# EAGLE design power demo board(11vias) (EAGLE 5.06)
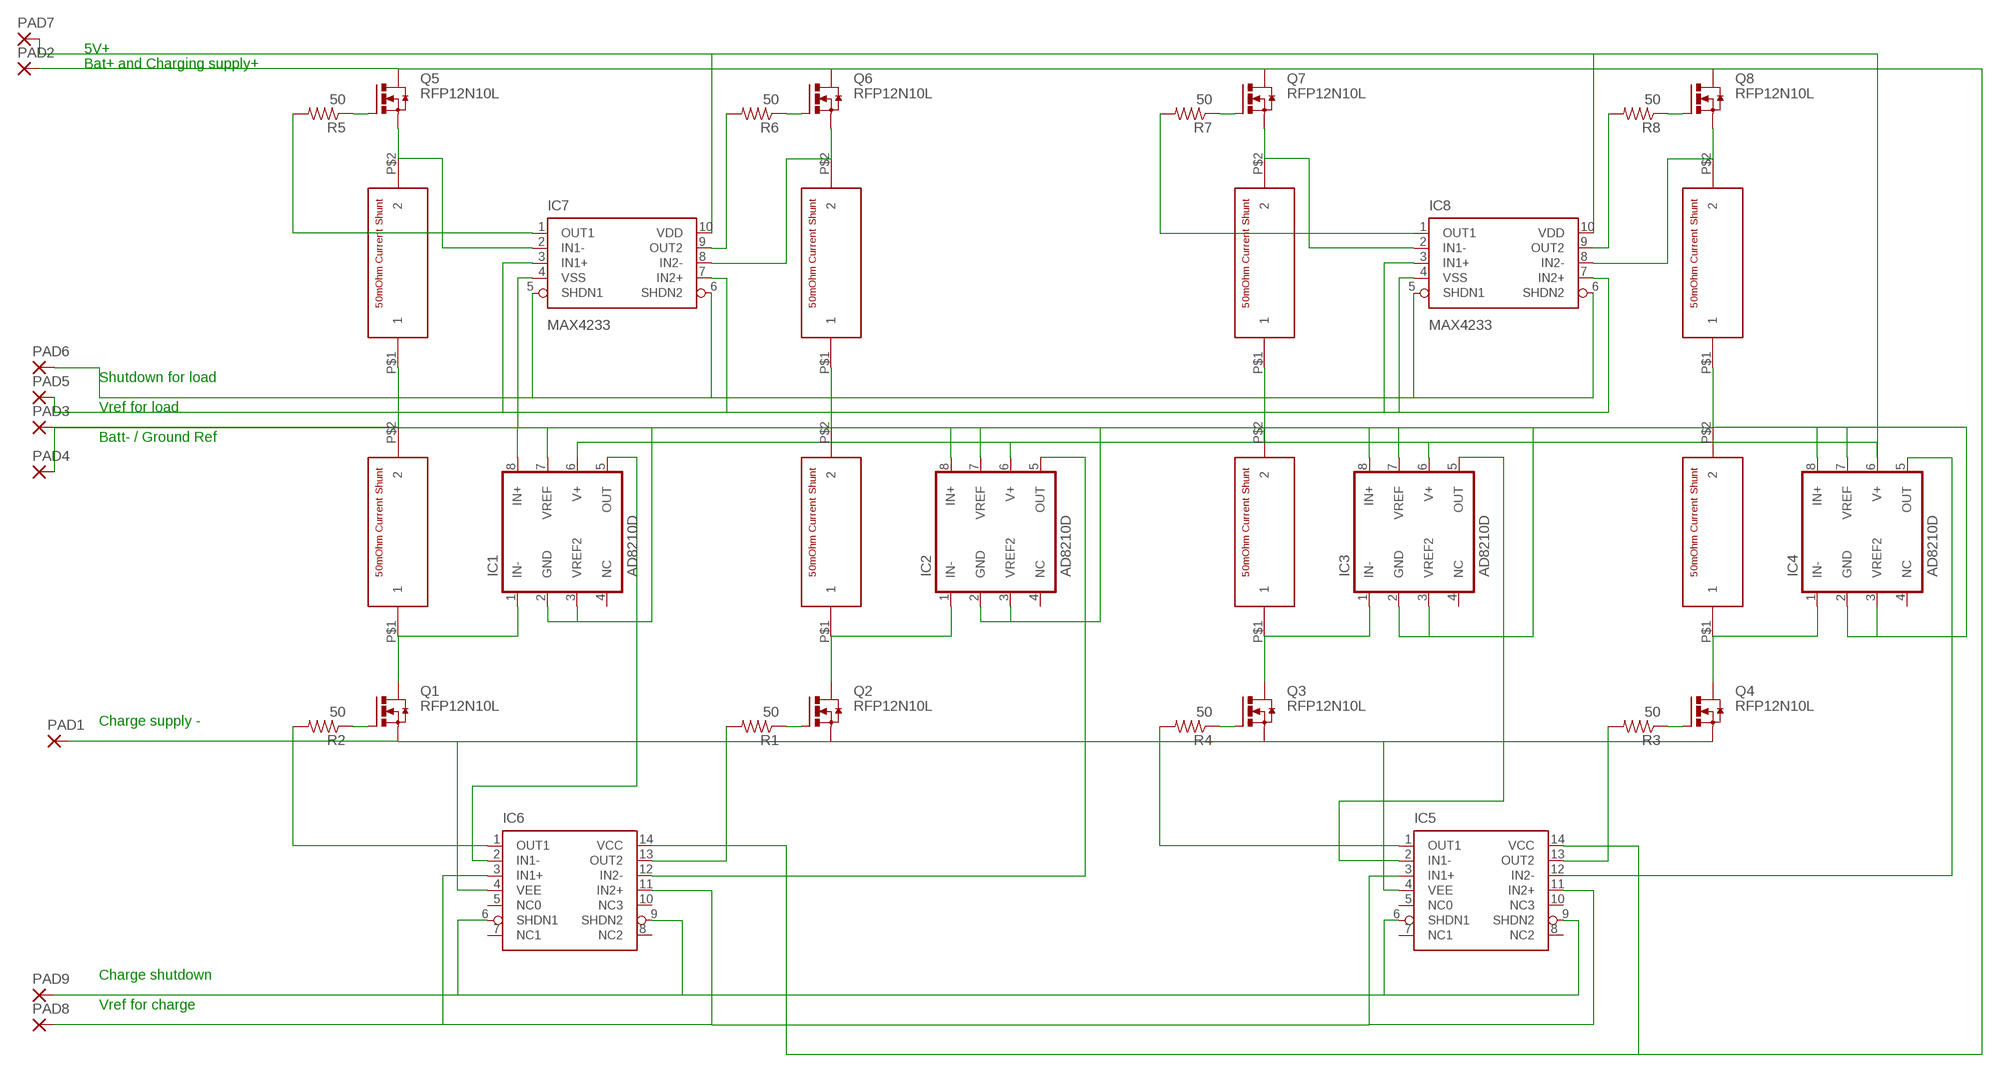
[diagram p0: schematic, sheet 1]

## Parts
IC1  AD8210D  [SO08]
IC2  AD8210D  [SO08]
IC3  AD8210D  [SO08]
IC4  AD8210D  [SO08]
IC5  MAX4168D  [SO14]
IC6  MAX4168D  [SO14]
IC7  MAX4233  [UMAX10]
IC8  MAX4233  [UMAX10]
PAD1  3,81/1,4  [3,81/1,4]
PAD2  3,81/1,4  [3,81/1,4]
PAD3  3,81/1,4  [3,81/1,4]
PAD4  3,81/1,4  [3,81/1,4]
PAD5  3,17/1,1  [3,17/1,1]
PAD6  3,17/1,1  [3,17/1,1]
PAD7  3,17/1,1  [3,17/1,1]
PAD8  3,17/1,1  [3,17/1,1]
PAD9  3,17/1,1  [3,17/1,1]
Q1  RFP12N10L  [TO220-W/657-20ABP]
Q2  RFP12N10L  [TO220-W/657-20ABP]
Q3  RFP12N10L  [TO220-W/657-20ABP]
Q4  RFP12N10L  [TO220-W/657-20ABP]
Q5  RFP12N10L  [TO220-W/657-20ABP]
Q6  RFP12N10L  [TO220-W/657-20ABP]
Q7  RFP12N10L  [TO220-W/657-20ABP]
Q8  RFP12N10L  [TO220-W/657-20ABP]
R1  50  R-US_0207/10  [0207/10]
R2  50  R-US_0207/10  [0207/10]
R3  50  R-US_0207/10  [0207/10]
R4  50  R-US_0207/10  [0207/10]
R5  50  R-US_0207/10  [0207/10]
R6  50  R-US_0207/10  [0207/10]
R7  50  R-US_0207/10  [0207/10]
R8  50  R-US_0207/10  [0207/10]
U$1  630HR050E  [630HR050E]
U$2  630HR050E  [630HR050E]
U$3  630HR050E  [630HR050E]
U$4  630HR050E  [630HR050E]
U$5  630HR050E  [630HR050E]
U$6  630HR050E  [630HR050E]
U$7  630HR050E  [630HR050E]
U$8  630HR050E  [630HR050E]

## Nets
N$1: IC5.13(OUT2) R3.2
N$2: IC1.1(IN-) Q1.2(D) U$5.P$1
N$3: IC2.1(IN-) Q2.2(D) U$6.P$1
N$4: IC3.1(IN-) Q3.2(D) U$7.P$1
N$5: IC7.3(IN1+) IC7.7(IN2+) IC8.3(IN1+) IC8.4(VSS) IC8.7(IN2+) PAD5.1(P)
N$6: IC5.4(VEE) IC6.4(VEE) PAD1.1(P) Q1.3(S) Q2.3(S) Q3.3(S) Q4.3(S)
N$7: IC7.2(IN1-) Q5.3(S) U$1.P$2
N$8: IC7.8(IN2-) Q6.3(S) U$2.P$2
N$9: IC8.2(IN1-) Q7.3(S) U$3.P$2
N$10: IC8.8(IN2-) Q8.3(S) U$4.P$2
N$11: IC5.14(VCC) IC6.14(VCC) PAD2.1(P) Q5.2(D) Q6.2(D) Q7.2(D) Q8.2(D)
N$12: IC7.1(OUT1) R5.2
N$13: Q5.1(G) R5.1
N$14: IC7.9(OUT2) R6.2
N$15: Q6.1(G) R6.1
N$16: Q7.1(G) R7.1
N$17: IC8.1(OUT1) R7.2
N$18: Q8.1(G) R8.1
N$19: IC8.9(OUT2) R8.2
N$20: IC7.5(SHDN1) IC7.6(SHDN2) IC8.5(SHDN1) IC8.6(SHDN2) PAD6.1(P)
N$21: IC4.1(IN-) Q4.2(D) U$8.P$1
N$22: IC5.6(SHDN1) IC5.9(SHDN2) IC6.6(SHDN1) IC6.9(SHDN2) PAD9.1(P)
N$23: IC6.13(OUT2) R1.2
N$24: Q1.1(G) R2.1
N$25: Q2.1(G) R1.1
N$26: Q3.1(G) R4.1
N$27: Q4.1(G) R3.1
N$28: IC5.1(OUT1) R4.2
N$29: IC2.5(OUT) IC6.12(IN2-)
N$31: IC5.3(IN1+) IC5.11(IN2+) IC6.3(IN1+) IC6.11(IN2+) PAD8.1(P)
N$32: IC1.5(OUT) IC6.2(IN1-)
N$33: IC6.1(OUT1) R2.2
N$34: IC4.5(OUT) IC5.12(IN2-)
N$35: IC3.5(OUT) IC5.2(IN1-)
N$36: IC1.2(GND) IC1.3(VREF2) IC1.7(VREF) IC1.8(IN+) IC2.2(GND) IC2.3(VREF2) IC2.7(VREF) IC2.8(IN+) IC3.2(GND) IC3.3(VREF2) IC3.7(VREF) IC3.8(IN+) IC4.2(GND) IC4.3(VREF2) IC4.7(VREF) IC4.8(IN+) IC7.4(VSS) PAD3.1(P) PAD4.1(P) U$1.P$1 U$2.P$1 U$3.P$1 U$4.P$1 U$5.P$2 U$6.P$2 U$7.P$2 U$8.P$2
N$40: IC1.6(V+) IC2.6(V+) IC3.6(V+) IC4.6(V+) IC7.10(VDD) IC8.10(VDD) PAD7.1(P)
Unconnected: IC5.5(NC0) IC5.7(NC1) IC5.10(NC3) IC6.5(NC0) IC6.7(NC1) IC6.10(NC3)

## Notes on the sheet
- 5V+
- Bat+ and Charging supply+
- Shutdown for load
- Vref for load
- Batt- / Ground Ref
- Charge supply -
- Charge shutdown
- Vref for charge

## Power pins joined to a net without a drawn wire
NC: IC1.4(NC) IC2.4(NC) IC3.4(NC) IC4.4(NC)
NC2: IC5.8(NC2) IC6.8(NC2)

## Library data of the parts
IC1-IC4 = NEWPARTS:AD8210: High Voltage, Bidirectional Current Shunt Monitor
IC5 IC6 = NEWPARTS:MAX4168: High-Output-Drive, Precision, Low-power, Single-Supply, Rail-to-Rail I/O Op Amps with Shutdown
IC7 IC8 = NEWPARTS:MAX4233: High-Output-Drive, 10MHz, 10V/us, Rail-to_rail I/O Op Amps with Shutdown in SC70
PAD1-PAD4 = wirepad:3,81/1,4: THROUGH-HOLE PAD
PAD5-PAD9 = wirepad:3,17/1,1: THROUGH-HOLE PAD
Q1-Q8 = NEWPARTS:RFP12N10L: N-Channel Power MOSFET 100V; 12A; 0,2Ohm< Logic Level
R1-R8 = rcl:R-US_: RESISTOR, American symbol
U$1-U$8 = NEWPARTS:630HR050E

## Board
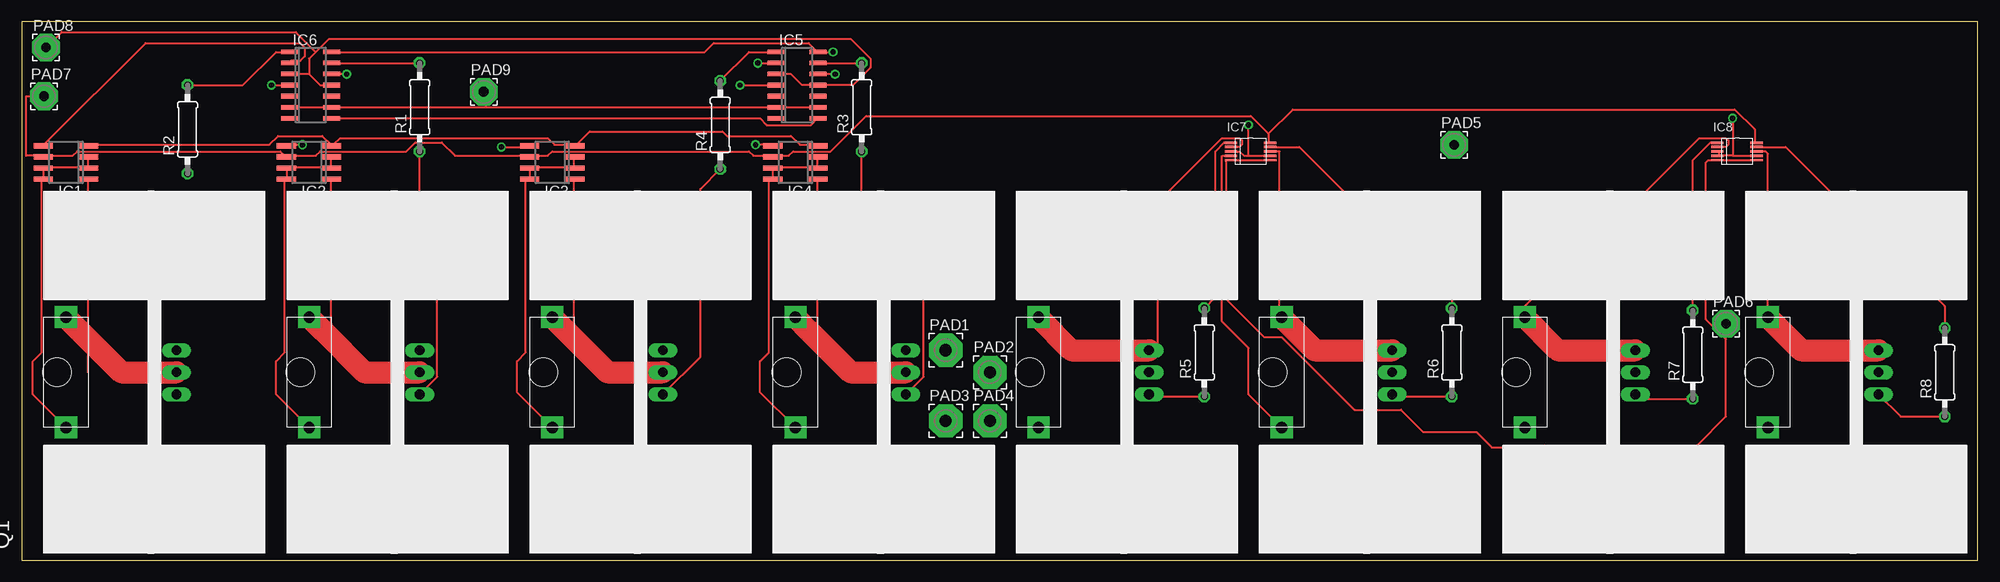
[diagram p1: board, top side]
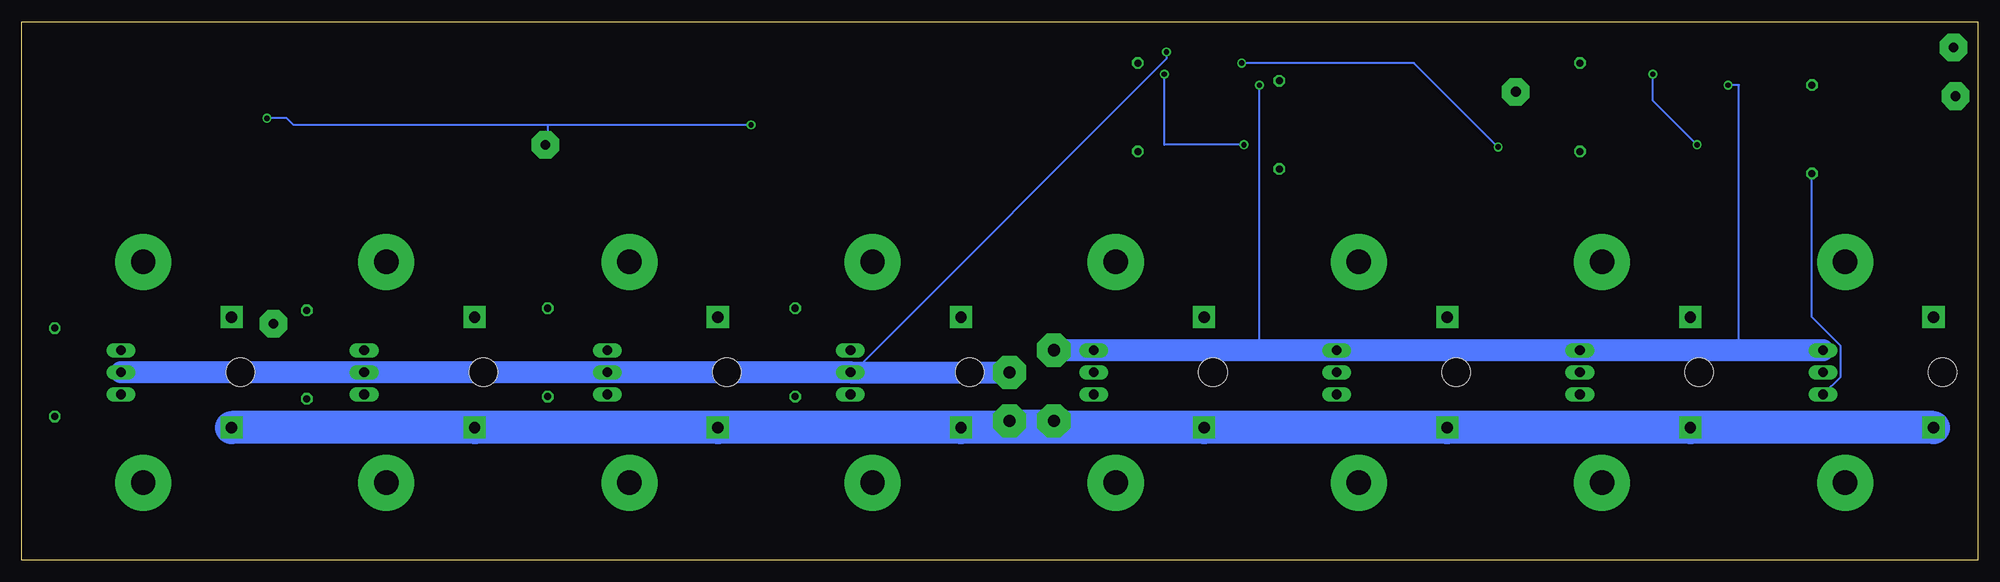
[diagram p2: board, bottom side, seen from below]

Size 224.77 x 61.9 mm. Coordinates in mm from the lower left corner, seen from the top.
Outline: 0,0 224.77,0 224.77,61.9 0,61.9 0,0
Copper layers (1*16): Top 0.035mm / dielectric 1.5mm / Bottom 0.035mm
Design rules "default *": minimum track width 10mil, minimum drill 24mil, track to track 10mil, track to pad 10mil, pad to pad 10mil, via to via 10mil, smd to smd 10mil, copper to edge 40mil, drill to drill 10mil, minimum pad ring 10mil, minimum via ring 8mil, stop-mask expansion 4mil, vias tented up to drill 0mil, thermal gap 10mil

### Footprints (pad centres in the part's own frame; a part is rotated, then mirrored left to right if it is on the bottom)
SO08 = smd 0.6 x 2.2: 1 -1.905,-2.6; 2 -0.635,-2.6; 3 0.635,-2.6; 4 1.905,-2.6; 5 1.905,2.6; 6 0.635,2.6; 7 -0.635,2.6; 8 -1.905,2.6
SO14 = smd 0.533 x 1.981: 1 -3.81,-2.219; 2 -2.54,-2.219; 3 -1.27,-2.219; 4 0,-2.219; 5 1.27,-2.219; 6 2.54,-2.219; 7 3.81,-2.219; 8 3.81,2.6; 9 2.54,2.6; 10 1.27,2.6; 11 0,2.6; 12 -1.27,2.6; 13 -2.54,2.6; 14 -3.81,2.6
UMAX10 = smd 0.28 x 1.4: 1 -1,-2; 2 -0.5,-2; 3 0,-2; 4 0.5,-2; 5 1,-2; 6 1,2.5; 7 0.5,2.5; 8 0,2.5; 9 -0.5,2.5; 10 -1,2.5
3,81/1,4 = drill 1.397 pad 3.81 octagon: 1 0,0
3,17/1,1 = drill 1.118 pad 3.175 octagon: 1 0,0
TO220-W/657-20ABP = drill 1.118 long: 1 -2.54,-2.54; 2 0,-2.54; 3 2.54,-2.54 | drill 2.8 pad 6.452 round: P$1 -12.7,0; P$2 12.7,0 | hole 3.302: 0,11.176
0207/10 = drill 0.813 octagon: 1 -5.08,0; 2 5.08,0
630HR050E = drill 1.3 pad 2.54 square: P$1 -6.35,0; P$2 6.35,0

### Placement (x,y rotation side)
IC1  5.08,45.72 90 top
IC2  33.02,45.72 90 top
IC3  60.96,45.72 90 top
IC4  88.9,45.72 90 top
IC5  88.9,54.61 270 top
IC6  33.02,54.61 270 top
IC7  140.97,46.99 270 top
IC8  196.85,46.99 270 top
PAD1  106.17,24.13 0 top
PAD2  111.25,21.59 0 top
PAD3  106.17,16 0 top
PAD4  111.25,16 0 top
PAD5  164.59,47.75 0 top
PAD6  195.83,27.18 0 top
PAD7  2.54,53.34 0 top
PAD8  2.79,58.93 0 top
PAD9  53.09,53.85 0 top
Q1  15.24,21.59 90 top
Q2  43.18,21.59 90 top
Q3  71.12,21.59 90 top
Q4  99.06,21.59 90 top
Q5  127,21.59 90 top
Q6  154.94,21.59 90 top
Q7  182.88,21.59 90 top
Q8  210.82,21.59 90 top
R1  45.72,52.07 90 top
R2  19.05,49.53 90 top
R3  96.52,52.07 90 top
R4  80.26,50.04 90 top
R5  135.89,23.88 90 top
R6  164.34,23.88 90 top
R7  192.02,23.62 90 top
R8  220.98,21.59 90 top
U$1  116.84,21.59 90 top
U$2  144.78,21.59 90 top
U$3  172.72,21.59 90 top
U$4  200.66,21.59 90 top
U$5  5.08,21.59 270 top
U$6  33.02,21.59 270 top
U$7  60.96,21.59 270 top
U$8  88.9,21.59 270 top

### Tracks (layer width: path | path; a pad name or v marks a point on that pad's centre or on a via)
N$1
  Top 0.254: 91.44,57.15 IC5.13 R3.2
N$2
  Top 0.254: IC1.1 7.62,43.69 7.62,27.18 | 7.62,21.59 7.62,27.18 | 7.62,27.18 6.73,26.29
  Top 2.54: Q1.2 11.43,21.59 6.73,26.29 U$5.P$1
N$3
  Top 0.254: 34.67,26.29 35.56,27.18 35.56,43.69 IC2.1
  Top 2.54: Q2.2 39.37,21.59 34.67,26.29 U$6.P$1
N$4
  Top 0.254: IC3.1 63.5,43.69 63.5,27.18 62.61,26.29
  Top 2.54: Q3.2 67.31,21.59 62.61,26.29 U$7.P$1
N$5  (via drill 0.61)
  Top 0.254: 140.97,46.48 140.46,46.48 139.95,46.99 IC7.3 | 140.97,46.48 143.26,46.48 IC7.7 | 195.07,46.48 195.07,46.99 IC8.3 | 196.6,46.48 195.07,46.48 | 196.6,46.48 199.14,46.48 IC8.7 | 195.07,46.48 IC8.4 | 140.97,46.48 v140.97,50.04 | v196.6,50.8 196.6,46.48
  Bottom 0.254: v140.97,50.04 164.34,50.04 | 164.34,50.04 193.55,50.04 194.31,50.8 v196.6,50.8 | PAD5.1 164.34,47.75 164.34,50.04
N$6  (via drill 0.6, 0.61)
  Top 0.254: v82.55,54.61 IC5.4 | v28.7,54.61 IC6.4
  Bottom 0.254: 27.43,24.13 27.43,54.61 v28.7,54.61 | 82.55,24.13 v82.55,54.61
  Bottom 2.54: Q1.3 27.43,24.13 Q2.3 Q3.3 82.55,24.13 Q4.3 PAD1.1
N$7
  Top 0.254: IC7.2 139.19,47.5 139.95,47.5 140.21,47.75 140.21,48.26 139.95,48.51 137.92,48.51 130.56,41.15 130.56,24.89 Q5.3
  Top 2.54: U$1.P$2 120.65,24.13 Q5.3
N$8
  Top 0.254: IC7.8 144.53,46.99 144.53,28.96 U$2.P$2
  Top 2.54: U$2.P$2 148.59,24.13 Q6.3
N$9
  Top 0.254: U$3.P$2 172.72,29.21 181.36,37.85 182.12,37.85 192.79,48.51 195.83,48.51 196.09,48.26 196.09,47.75 195.83,47.5 195.07,47.5 IC8.2
  Top 2.54: U$3.P$2 176.53,24.13 Q7.3
N$10
  Top 0.254: U$4.P$2 200.66,46.74 200.41,46.99 IC8.8
  Top 2.54: U$4.P$2 204.47,24.13 Q8.3
N$11  (via drill 0.61)
  Top 0.254: 35.56,58.42 IC6.14 78.49,58.42 79.5,59.44 90.42,59.44 91.44,58.42 IC5.14 v93.22,58.42
  Bottom 0.254: v93.22,58.42 93.22,57.66 128.52,22.35 Q5.2
  Bottom 2.54: Q8.2 Q7.2 Q6.2 Q5.2 PAD2.1
N$12
  Top 0.254: IC7.1 138.94,48.01 138.18,48.01 137.16,46.99 137.16,30.23 R5.2
N$13
  Top 0.254: R5.1 129.79,18.8 Q5.1
N$14
  Top 0.254: R6.2 164.34,29.97 146.81,47.5 143.51,47.5 IC7.9
N$15
  Top 0.254: R6.1 157.73,18.8 Q6.1
N$16
  Top 0.254: R7.1 185.93,18.54 Q7.1
N$17
  Top 0.254: R7.2 192.02,45.97 194.06,48.01 194.82,48.01 IC8.1
N$18
  Top 0.254: R8.1 215.9,16.51 Q8.1
N$19
  Top 0.254: R8.2 220.98,29.21 202.69,47.5 199.39,47.5 IC8.9
N$20
  Top 0.254: IC7.6 143.26,45.97 139.19,45.97 IC7.5 138.94,45.97 138.43,45.97 138.43,29.97 142.75,25.65 144.78,25.65 153.16,17.27 158.5,17.27 161.04,14.73 167.13,14.73 168.91,12.95 174.75,12.95 175.01,13.21 192.53,13.21 195.83,16.51 195.83,25.4 | IC8.6 199.14,45.97 195.07,45.97 IC8.5 194.82,45.97 193.8,45.97 193.55,45.72 193.55,27.69 195.83,25.4 | 195.83,25.4 PAD6.1
N$21
  Top 0.254: IC4.1 91.44,43.69 91.44,27.18 90.55,26.29
  Top 2.54: Q4.2 95.25,21.59 90.55,26.29 U$8.P$1
N$22
  Top 0.254: IC5.9 IC5.6 53.34,52.07 | IC6.6 IC6.9 53.34,52.07 | PAD9.1 53.34,53.85 53.34,52.07
N$23
  Top 0.254: 35.56,57.15 IC6.13 R1.2
N$24
  Bottom 0.254: R2.1 19.05,27.94 15.75,24.64 15.75,21.08 Q1.1
N$25
  Top 0.254: R1.1 45.72,36.83 47.75,34.8 47.75,21.08 Q2.1
N$26
  Top 0.254: Q3.1 77.98,23.37 77.98,42.67 R4.1
N$27
  Top 0.254: R3.1 96.52,41.91 103.63,34.8 103.63,21.08 Q4.1
N$28
  Top 0.254: R4.2 83.57,58.42 IC5.1
N$29  (via drill 0.61)
  Top 0.254: v32.26,47.75 30.48,47.75 IC2.5 | v37.34,55.88 IC6.12
  Bottom 0.254: v37.34,55.88 37.34,52.83 v32.26,47.75
N$31
  Top 0.254: 33.02,55.88 34.29,54.61 IC6.11 | 33.02,55.88 IC6.3 | IC5.3 88.39,55.88 89.66,54.61 IC5.11 95.5,54.61 97.54,56.64 97.54,57.66 95.25,59.94 35.31,59.94 33.78,58.42 | 33.02,55.88 33.02,57.66 33.78,58.42 | 33.78,58.42 31.5,60.71 4.57,60.71 PAD8.1
N$32
  Top 0.254: IC6.2 30.99,57.4 32,57.4 32.51,57.91 32.51,58.93 32,59.44 14.22,59.44 2.54,47.75 IC1.5
N$33
  Top 0.254: R2.2 25.4,54.61 29.21,58.42 IC6.1
N$34  (via drill 0.61)
  Top 0.254: v84.33,47.75 86.36,47.75 IC4.5 | v93.47,55.88 IC5.12
  Bottom 0.254: v84.33,47.75 93.47,47.75 v93.47,55.88
N$35  (via drill 0.61)
  Top 0.254: v55.12,47.5 58.42,47.5 IC3.5 | v84.58,57.15 IC5.2
  Bottom 0.254: v55.12,47.5 64.77,57.15 v84.58,57.15
N$36
  Top 0.254: 86.36,45.21 86.36,43.69 IC4.8 85.85,43.69 85.85,23.88 84.84,22.86 84.84,19.3 U$8.P$2 | 91.44,45.21 91.44,46.23 IC4.3 | 86.36,45.21 91.44,45.21 | 86.36,45.21 IC4.7 | 91.44,45.21 IC4.2 | 58.42,45.21 58.42,43.69 IC3.8 57.91,43.69 57.91,23.88 56.9,22.86 56.9,19.3 U$7.P$2 | 63.5,45.21 63.5,46.23 IC3.3 | 58.42,45.21 63.5,45.21 | 58.42,45.21 IC3.7 | 63.5,45.21 IC3.2 | 30.48,45.21 30.48,43.69 IC2.8 30.23,43.69 30.23,23.88 29.21,22.86 29.21,19.05 U$6.P$2 | 35.56,45.21 35.56,46.23 IC2.3 | 30.48,45.21 35.56,45.21 | 30.48,45.21 IC2.7 | 35.56,45.21 IC2.2 | 2.54,45.21 2.54,43.69 IC1.8 2.29,43.69 2.29,23.88 1.27,22.86 1.27,19.05 U$5.P$2 | 7.62,45.21 7.62,46.23 IC1.3 | 2.54,45.21 7.62,45.21 | 2.54,45.21 IC1.7 | 7.62,45.21 IC1.2 | U$2.P$1 140.97,19.05 140.97,24.38 137.92,27.43 137.92,46.48 138.94,46.48 IC7.4
  Bottom 2.54: PAD3.1 PAD4.1 111.25,15.24 U$1.P$1
  Bottom 3.81: U$5.P$2 U$6.P$2 U$7.P$2 U$8.P$2 U$1.P$1 U$2.P$1 U$3.P$1 U$4.P$1
N$40
  Top 0.254: 143.26,49.02 143.26,48.01 IC7.10 | 143.26,49.02 141.22,51.05 97.03,51.05 92.96,46.99 88.65,46.99 88.14,46.48 86.36,46.48 IC4.6 86.11,46.48 84.07,46.48 83.57,46.99 60.96,46.99 60.45,46.48 58.42,46.48 IC3.6 58.17,46.48 49.78,46.48 48.26,48.01 45.21,48.01 44.2,46.99 34.29,46.99 33.78,46.48 30.48,46.48 IC2.6 30.23,46.48 29.72,46.99 6.35,46.99 5.84,46.48 2.54,46.48 IC1.6 2.48,46.48 0.51,46.48 0.51,53.34 PAD7.1 | 143.26,49.02 146.05,51.82 196.85,51.82 199.14,49.53 199.14,48.01 IC8.10
NC
  Top 0.254: IC4.4 91.44,47.75 89.41,47.75 88.39,48.77 81.03,48.77 80.52,49.28 65.28,49.28 63.75,47.75 IC3.4 63.5,47.75 61.21,47.75 60.45,48.51 36.58,48.51 35.81,47.75 IC2.4 35.56,47.75 34.54,48.77 29.46,48.77 28.45,47.75 7.87,47.75 IC1.4
NC2
  Top 0.254: IC6.8 84.84,50.8 85.6,50.04 90.68,50.04 91.44,50.8 IC5.8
